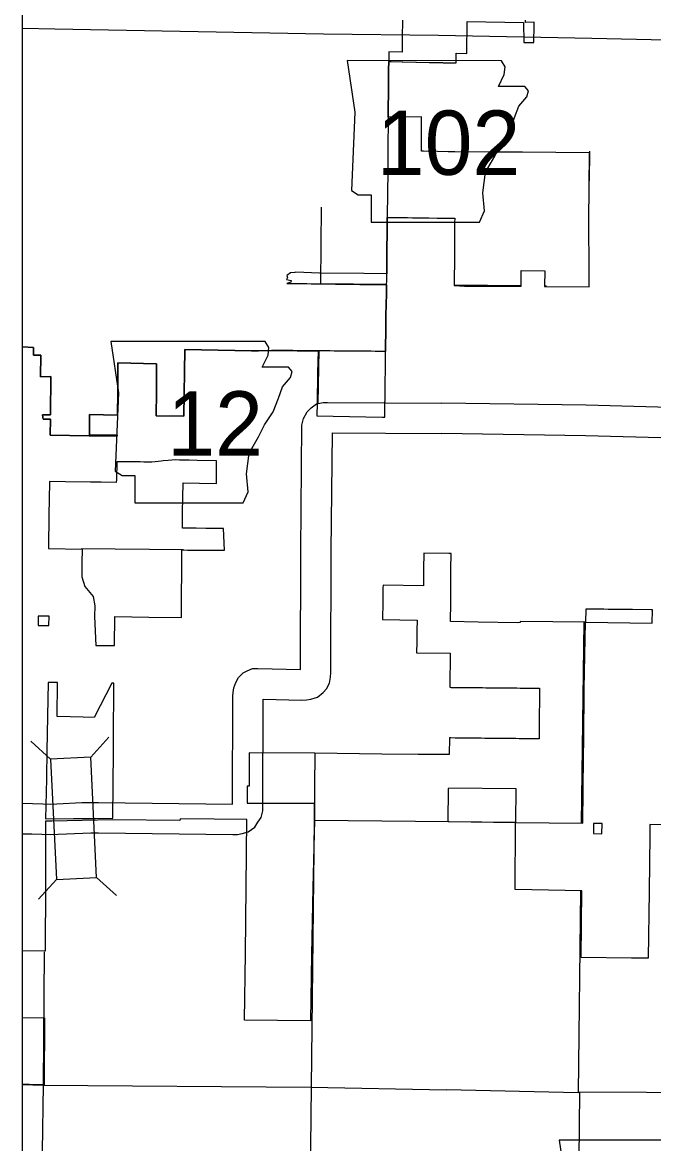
# Model space of a CAD drawing. Extents: x 309389.3 to 309420.2, y 336441.4 to 336461.2.
# Drawn here: x 309389.335 to 309390.277, y 336456.181 to 336457.854 of the extents above; entities that cross this region are included whole.
import ezdxf

# ---------------------------------------------------------------- set-up
doc = ezdxf.new("R2010")
doc.units = 0
for name, color, linetype in [('Level 24', 7, 'Continuous'), ('Level 37', 7, 'Continuous'), ('Level 4', 7, 'Continuous'), ('Level 62', 7, 'Continuous'), ('R_Contours', 7, 'Continuous'), ('R_MOT', 7, 'Continuous')]:
    doc.layers.add(name, color=color, linetype=linetype)

msp = doc.modelspace()

# ---------------------------------------------------------------- linework, layer by layer
at = {"layer": 'Level 24'}
for points in [[(309389.9561, 336457.8344), (309389.7843, 336457.8364), (309389.3834, 336457.8438), (309389.3351, 336457.8447)], [(309390.7673, 336457.8202), (309390.584, 336457.821), (309390.1849, 336457.8299), (309389.956, 336457.8344)], [(309389.3351, 336456.6888), (309389.3501, 336456.6885), (309389.3657, 336456.6881), (309389.3767, 336456.6876), (309389.3865, 336456.6879), (309389.424, 336456.6897), (309389.4366, 336456.6899), (309389.4487, 336456.6899), (309389.6486, 336456.6876), (309389.6492, 336456.8486), (309389.6496, 336456.8538), (309389.6506, 336456.8612), (309389.6535, 336456.8688), (309389.6575, 336456.8766), (309389.6648, 336456.8834), (309389.6706, 336456.8866), (309389.6784, 336456.8898), (309389.6867, 336456.8899), (309389.7499, 336456.8884), (309389.7506, 336457.0651), (309389.7523, 336457.253), (309389.7548, 336457.263), (309389.7599, 336457.273), (309389.7661, 336457.2789), (309389.7742, 336457.2848), (309389.7842, 336457.2867), (309389.7905, 336457.2869), (309389.8775, 336457.2863)], [(309389.8775, 336457.2863), (309389.9611, 336457.2858)], [(309390.8213, 336457.2733), (309390.5801, 336457.2731), (309390.5679, 336457.2721), (309390.1765, 336457.2827), (309389.9613, 336457.2858)], [(309389.3351, 336456.6433), (309389.3491, 336456.643), (309389.364, 336456.6427), (309389.3763, 336456.6421), (309389.3883, 336456.6424), (309389.4255, 336456.6442), (309389.437, 336456.6444), (309389.4485, 336456.6445), (309389.6493, 336456.6421), (309389.656, 336456.6423), (309389.6633, 336456.6434), (309389.6722, 336456.6463), (309389.6821, 336456.6532), (309389.6867, 336456.6604), (309389.6912, 336456.6673), (309389.6937, 336456.6775), (309389.6941, 336456.6851), (309389.6946, 336456.8442), (309389.752, 336456.8428), (309389.7589, 336456.8433), (309389.7657, 336456.8443), (309389.7757, 336456.8473), (309389.7838, 336456.854), (309389.789, 336456.8596), (309389.7934, 336456.8681), (309389.7951, 336456.877), (309389.7953, 336456.8841), (309389.7961, 336457.0648), (309389.7977, 336457.2414), (309389.8772, 336457.2409)], [(309389.8772, 336457.2409), (309389.9608, 336457.2403)], [(309390.8895, 336457.228), (309390.8636, 336457.2278), (309390.8461, 336457.2279), (309390.5819, 336457.2276), (309390.569, 336457.2266), (309390.1755, 336457.2373), (309389.9606, 336457.2403)]]:
    msp.add_lwpolyline(points, dxfattribs=at)
at = {"layer": 'Level 37'}
for p, q in [((309389.3772, 336456.7548), (309389.3476, 336456.7816)), ((309389.4371, 336456.7577), (309389.464, 336456.7873)), ((309389.386, 336456.575), (309389.3591, 336456.5454)), ((309389.4459, 336456.5779), (309389.4755, 336456.551))]:
    msp.add_line(p, q, dxfattribs=at)
msp.add_lwpolyline([(309389.3772, 336456.7548), (309389.386, 336456.575), (309389.4459, 336456.5779), (309389.4371, 336456.7577)], close=True, dxfattribs=at)
at = {"layer": 'Level 4'}
for points in [[(309390.1813, 336457.662), (309390.1807, 336457.6178)], [(309389.7809, 336457.5784), (309389.7799, 336457.4651)], [(309389.7799, 336457.4645), (309389.8787, 336457.4632)], [(309390.0793, 336457.4608), (309389.9796, 336457.4619)], [(309390.1175, 336457.4603), (309390.1144, 336457.4604)], [(309389.7777, 336457.3651), (309389.776, 336457.2857)], [(309389.5756, 336457.0667), (309389.4228, 336457.0682)], [(309390.1729, 336456.9592), (309390.1691, 336456.6591)], [(309389.7714, 336456.7636), (309389.7706, 336456.6632), (309389.766, 336456.2656), (309389.7616, 336455.8654), (309389.7546, 336455.4639)], [(309389.9722, 336456.661), (309389.7709, 336456.6629)], [(309390.0712, 336456.6598), (309389.9722, 336456.661)], [(309390.2001, 336456.6583), (309390.1875, 336456.6584)], [(309390.1679, 336456.5581), (309390.1643, 336456.2566)], [(309389.3572, 336455.4699), (309389.3608, 336455.8707), (309389.3666, 336456.2688), (309389.3681, 336456.467)], [(309389.3351, 336456.2689), (309389.3663, 336456.2683), (309389.7656, 336456.2653), (309389.968, 336456.2612)], [(309390.1643, 336456.2566), (309389.968, 336456.2612)]]:
    msp.add_lwpolyline(points, dxfattribs=at)
at = {"layer": 'Level 62'}
for points in [[(309389.9022, 336457.8575), (309389.902, 336457.8314), (309389.902, 336457.8098), (309389.8819, 336457.8099), (309389.8818, 336457.7957), (309389.8817, 336457.7833), (309389.8816, 336457.7731), (309389.8815, 336457.763), (309389.8811, 336457.7127), (309389.8807, 336457.6626), (309389.8803, 336457.6311), (309389.88, 336457.5997), (309389.8799, 336457.5968), (309389.8798, 336457.5851), (309389.8797, 336457.5776), (309389.8796, 336457.5643), (309389.8795, 336457.5631), (309389.8795, 336457.5543), (309389.8793, 336457.5323), (309389.8792, 336457.5229), (309389.8791, 336457.5131), (309389.8791, 336457.5074), (309389.879, 336457.4946), (309389.8789, 336457.4789), (309389.8445, 336457.4792), (309389.7786, 336457.48), (309389.743, 336457.4811), (309389.7417, 336457.4807), (309389.735, 336457.4804), (309389.7299, 336457.4761), (309389.7307, 336457.4732), (309389.7293, 336457.4701), (309389.7363, 336457.4687), (309389.7357, 336457.4662), (309389.7298, 336457.4646), (309389.7341, 336457.4645), (309389.7377, 336457.4646), (309389.7416, 336457.4644), (309389.7477, 336457.4644), (309389.7537, 336457.4643), (309389.7598, 336457.4642), (309389.7659, 336457.4641), (309389.7719, 336457.464), (309389.778, 336457.464), (309389.7789, 336457.4639), (309389.7841, 336457.4639), (309389.7901, 336457.4638), (309389.7961, 336457.4637), (309389.8022, 336457.4636), (309389.8082, 336457.4635), (309389.8143, 336457.4635), (309389.8203, 336457.4634), (309389.8263, 336457.4633), (309389.8324, 336457.4632), (309389.8385, 336457.4631), (309389.8446, 336457.4631), (309389.8506, 336457.463), (309389.8567, 336457.4629), (309389.8628, 336457.4628), (309389.8689, 336457.4627), (309389.8757, 336457.4627), (309389.8787, 336457.4625), (309389.8786, 336457.4538), (309389.8785, 336457.4533), (309389.8784, 336457.4463), (309389.8782, 336457.4356), (309389.8777, 336457.4145)], [(309389.8852, 336457.7956), (309389.9019, 336457.7953), (309389.9031, 336457.7953), (309389.9224, 336457.7948), (309389.9235, 336457.7948), (309389.9422, 336457.7944), (309389.9436, 336457.7944), (309389.9623, 336457.794), (309389.9633, 336457.7939), (309389.9825, 336457.7935), (309389.9826, 336457.8081), (309389.9986, 336457.8076), (309389.9987, 336457.8555), (309390.0831, 336457.8538), (309390.0834, 336457.8242), (309390.0985, 336457.8238), (309390.0989, 336457.8496), (309390.0989, 336457.8541), (309390.0858, 336457.8538), (309390.0858, 336457.8574)], [(309389.5348, 336457.2669), (309389.5761, 336457.2663), (309389.5774, 336457.3659), (309389.6772, 336457.3639), (309389.6873, 336457.3638), (309389.7068, 336457.3644), (309389.7183, 336457.3643), (309389.7197, 336457.3643), (309389.7259, 336457.3643), (309389.7323, 336457.3642), (309389.7387, 336457.3642), (309389.7451, 336457.3641), (309389.7472, 336457.3641), (309389.7519, 336457.364), (309389.758, 336457.364), (309389.7641, 336457.3639), (309389.7702, 336457.3639), (309389.7757, 336457.3638), (309389.7763, 336457.3638), (309389.7757, 336457.3309), (309389.7757, 336457.3303), (309389.775, 336457.2861), (309389.7747, 336457.2667), (309389.8721, 336457.2648), (309389.8761, 336457.2647), (309389.8766, 336457.3122), (309389.8769, 336457.3411), (309389.8771, 336457.363), (309389.8772, 336457.3677), (309389.8775, 336457.3951), (309389.8777, 336457.4145), (309389.8782, 336457.4356), (309389.8784, 336457.4463), (309389.8785, 336457.4533), (309389.8786, 336457.4538), (309389.8787, 336457.4625), (309389.8787, 336457.4629), (309389.8788, 336457.468), (309389.8789, 336457.4789), (309389.879, 336457.4946), (309389.8791, 336457.5091), (309389.8791, 336457.5131), (309389.8792, 336457.5229), (309389.8793, 336457.5323), (309389.8795, 336457.5543), (309389.8795, 336457.5631), (309389.8834, 336457.5631), (309389.8915, 336457.5629), (309389.9095, 336457.5627), (309389.9099, 336457.5627), (309389.9171, 336457.5626), (309389.9241, 336457.5625), (309389.9325, 336457.5624), (309389.9416, 336457.5623), (309389.9539, 336457.5621), (309389.9543, 336457.5621), (309389.9662, 336457.562), (309389.9699, 336457.5619), (309389.9803, 336457.5618), (309389.9802, 336457.5548), (309389.9802, 336457.5475), (309389.9801, 336457.5408), (309389.9801, 336457.5332), (309389.98, 336457.5297), (309389.98, 336457.5222), (309389.9799, 336457.5153), (309389.9799, 336457.5083), (309389.9799, 336457.5015), (309389.9798, 336457.4947), (309389.9798, 336457.4879), (309389.9797, 336457.4811), (309389.9797, 336457.4752), (309389.9796, 336457.4694), (309389.9796, 336457.4616), (309389.9796, 336457.4614), (309389.9951, 336457.4602), (309390.0793, 336457.4605), (309390.0795, 336457.4836), (309390.1146, 336457.4834), (309390.1147, 336457.4832), (309390.1144, 336457.4601), (309390.1808, 336457.4592), (309390.1809, 336457.4828), (309390.1803, 336457.5574), (309390.1814, 336457.6594), (309390.1313, 336457.6598), (309390.0815, 336457.6604), (309390.045, 336457.6606), (309389.9803, 336457.6609), (309389.9703, 336457.661), (309389.9546, 336457.6614), (309389.9337, 336457.6617), (309389.9305, 336457.6617), (309389.9305, 336457.7129), (309389.8811, 336457.7127), (309389.8815, 336457.763), (309389.8816, 336457.7731), (309389.8817, 336457.7833), (309389.8818, 336457.7957), (309389.8852, 336457.7956)], [(309389.8777, 336457.4145), (309389.8775, 336457.3951), (309389.8772, 336457.3677), (309389.8771, 336457.363), (309389.8745, 336457.363), (309389.8677, 336457.363), (309389.8616, 336457.3631), (309389.8555, 336457.3632), (309389.8494, 336457.3632), (309389.8433, 336457.3633), (309389.8372, 336457.3633), (309389.8311, 336457.3634), (309389.825, 336457.3634), (309389.8189, 336457.3635), (309389.8128, 336457.3635), (309389.8067, 336457.3636), (309389.8006, 336457.3636), (309389.7945, 336457.3637), (309389.7885, 336457.3637), (309389.7824, 336457.3638), (309389.777, 336457.3638), (309389.7763, 336457.3638), (309389.7757, 336457.3638), (309389.7702, 336457.3639), (309389.7641, 336457.3639), (309389.758, 336457.364), (309389.7519, 336457.364), (309389.7472, 336457.3641), (309389.7451, 336457.3641), (309389.7387, 336457.3642), (309389.7323, 336457.3642), (309389.7259, 336457.3643), (309389.7197, 336457.3643), (309389.7183, 336457.3643), (309389.7068, 336457.3644), (309389.6873, 336457.3638), (309389.6772, 336457.3639), (309389.5774, 336457.3659), (309389.5761, 336457.2663), (309389.5348, 336457.2669), (309389.5348, 336457.2685), (309389.5351, 336457.3012), (309389.5353, 336457.3229), (309389.5354, 336457.3445), (309389.4776, 336457.3462), (309389.4775, 336457.3245), (309389.4773, 336457.3028), (309389.4771, 336457.2677), (309389.4351, 336457.2688), (309389.435, 336457.2386), (309389.4766, 336457.2378), (309389.4765, 336457.2364), (309389.4349, 336457.2373), (309389.3766, 336457.2379), (309389.3769, 336457.2619), (309389.3661, 336457.2617), (309389.3656, 336457.2651), (309389.365, 336457.2685), (309389.3708, 336457.2683), (309389.377, 336457.2682), (309389.377, 336457.2691), (309389.3775, 336457.3254), (309389.3621, 336457.3253), (309389.3625, 336457.3572), (309389.3518, 336457.3574), (309389.3519, 336457.3691), (309389.3351, 336457.3697)], [(309389.3351, 336457.3697), (309389.3519, 336457.3691), (309389.3518, 336457.3574), (309389.3625, 336457.3572), (309389.3621, 336457.3253), (309389.3775, 336457.3254), (309389.377, 336457.2691), (309389.377, 336457.2682), (309389.3708, 336457.2683), (309389.365, 336457.2685), (309389.3656, 336457.2651), (309389.3661, 336457.2617), (309389.3769, 336457.2619), (309389.3766, 336457.2379), (309389.4349, 336457.2373), (309389.4765, 336457.2364), (309389.4766, 336457.2378), (309389.435, 336457.2386), (309389.4351, 336457.2688), (309389.4771, 336457.2677), (309389.4773, 336457.3028), (309389.4775, 336457.3245), (309389.4776, 336457.3462), (309389.5354, 336457.3445), (309389.5353, 336457.3229), (309389.5351, 336457.3012), (309389.5348, 336457.2685), (309389.5348, 336457.2669)], [(309390.169, 336456.4586), (309390.1702, 336456.5581), (309390.0703, 336456.56), (309390.0712, 336456.6575), (309390.0712, 336456.6602), (309390.0712, 336456.6602), (309390.1715, 336456.659), (309390.172, 336456.7095), (309390.1726, 336456.7586), (309390.1729, 336456.7839), (309390.1737, 336456.8597), (309390.1756, 336456.9592), (309390.0781, 336456.9599), (309390.078, 336456.9583), (309390.0745, 336456.9582), (309390.0154, 336456.9591), (309389.9742, 336456.9598), (309389.9742, 336456.9613), (309389.9744, 336456.987), (309389.9745, 336457.0127), (309389.9747, 336457.0383), (309389.9748, 336457.0614), (309389.9716, 336457.0614), (309389.934, 336457.0619), (309389.9338, 336457.0386), (309389.9335, 336457.0133), (309389.8733, 336457.0141), (309389.8732, 336457.0102), (309389.8732, 336457.0034), (309389.873, 336456.9923), (309389.873, 336456.989), (309389.8725, 336456.9628), (309389.9242, 336456.962), (309389.924, 336456.9465), (309389.9237, 336456.9298), (309389.9235, 336456.913), (309389.9736, 336456.9125), (309389.9729, 336456.8618), (309389.9752, 336456.8617), (309389.9815, 336456.8617), (309389.9862, 336456.8616), (309389.991, 336456.8616), (309389.9958, 336456.8615), (309390.0015, 336456.8615), (309390.0072, 336456.8614), (309390.0121, 336456.8614), (309390.017, 336456.8613), (309390.022, 336456.8613), (309390.0269, 336456.8612), (309390.0319, 336456.8612), (309390.0376, 336456.8611), (309390.0414, 336456.8611), (309390.0473, 336456.861), (309390.0524, 336456.861), (309390.0576, 336456.8609), (309390.0628, 336456.8609), (309390.0679, 336456.8608), (309390.0731, 336456.8608), (309390.0782, 336456.8607), (309390.0833, 336456.8607), (309390.0885, 336456.8606), (309390.0944, 336456.8605), (309390.0981, 336456.8605), (309390.1068, 336456.8604), (309390.1067, 336456.8526), (309390.1067, 336456.8488), (309390.1066, 336456.843), (309390.1066, 336456.838), (309390.1066, 336456.8331), (309390.1065, 336456.8282), (309390.1065, 336456.8233), (309390.1065, 336456.8183), (309390.1064, 336456.8134), (309390.1064, 336456.8085), (309390.1064, 336456.8036), (309390.1063, 336456.7989), (309390.1063, 336456.7906), (309390.1062, 336456.7848), (309390.0998, 336456.7849), (309390.0914, 336456.785), (309390.0865, 336456.785), (309390.0815, 336456.7851), (309390.0766, 336456.7851), (309390.0717, 336456.7852), (309390.0668, 336456.7852), (309390.0618, 336456.7853), (309390.0569, 336456.7853), (309390.052, 336456.7854), (309390.047, 336456.7854), (309390.0406, 336456.7855), (309390.0368, 336456.7855), (309390.0304, 336456.7856), (309390.0251, 336456.7856), (309390.0198, 336456.7857), (309390.0145, 336456.7858), (309390.0092, 336456.7858), (309390.0039, 336456.7859), (309389.9986, 336456.7859), (309389.9932, 336456.786), (309389.9871, 336456.786)], [(309389.9871, 336456.786), (309389.9811, 336456.7861), (309389.9746, 336456.7862), (309389.9723, 336456.7862), (309389.9718, 336456.7613), (309389.9255, 336456.7617), (309389.8716, 336456.7622), (309389.7715, 336456.7637), (309389.6737, 336456.7641), (309389.6734, 336456.7144), (309389.6706, 336456.7143), (309389.6703, 336456.6891), (309389.7711, 336456.6888), (309389.7711, 336456.687), (309389.771, 336456.6635), (309389.7687, 336456.5627), (309389.7677, 336456.5127), (309389.7668, 336456.4633), (309389.7653, 336456.3641), (309389.6667, 336456.3652), (309389.6679, 336456.4645), (309389.6689, 336456.5638), (309389.67, 336456.6646), (309389.6211, 336456.665), (309389.5704, 336456.6656), (309389.5703, 336456.6632), (309389.4701, 336456.664), (309389.379, 336456.6622), (309389.3698, 336456.662), (309389.3696, 336456.5682), (309389.3691, 336456.4679), (309389.3351, 336456.4683)], [(309390.4672, 336456.6764), (309390.4198, 336456.6769), (309390.419, 336456.6571), (309390.419, 336456.6554), (309390.3703, 336456.6563), (309390.3455, 336456.6565), (309390.2715, 336456.657), (309390.2715, 336456.6536), (309390.2713, 336456.6413), (309390.2703, 336456.5572), (309390.269, 336456.4574), (309390.2439, 336456.4577), (309390.169, 336456.4586)], [(309390.3681, 336456.4556), (309390.3532, 336456.4559), (309390.2938, 336456.457), (309390.2933, 336456.4094), (309390.2926, 336456.3561), (309390.3666, 336456.3549), (309390.3656, 336456.2793), (309390.3653, 336456.2551), (309390.2663, 336456.2569), (309390.1664, 336456.2575), (309390.1654, 336456.1577), (309390.1645, 336456.1081), (309390.1637, 336456.0585), (309390.2387, 336456.0577), (309390.24, 336456.1563), (309390.2653, 336456.1558), (309390.2641, 336456.0881), (309390.3639, 336456.0872), (309390.3635, 336456.0559)], [(309389.3351, 336456.3692), (309389.3679, 336456.3685), (309389.3674, 336456.2687), (309389.345, 336456.269), (309389.3351, 336456.2691)]]:
    msp.add_lwpolyline(points, dxfattribs=at)
for points in [[(309389.4725, 336456.9242), (309389.4731, 336456.9673), (309389.5236, 336456.9666), (309389.5724, 336456.966), (309389.5731, 336457.0667), (309389.5813, 336457.0666), (309389.5942, 336457.0665), (309389.6096, 336457.0664), (309389.6104, 336457.0664), (309389.615, 336457.0664), (309389.6263, 336457.0663), (309389.6365, 336457.0662), (309389.6354, 336457.0988), (309389.6087, 336457.0989), (309389.5945, 336457.0992), (309389.5738, 336457.0993), (309389.5738, 336457.1033), (309389.5742, 336457.1226), (309389.575, 336457.1667), (309389.5994, 336457.1664), (309389.6246, 336457.166), (309389.6246, 336457.1716), (309389.6247, 336457.1823), (309389.6247, 336457.1879), (309389.6248, 336457.1928), (309389.6248, 336457.1999), (309389.5957, 336457.2004), (309389.5839, 336457.2005), (309389.5809, 336457.2006), (309389.5751, 336457.2007), (309389.5695, 336457.2008), (309389.5638, 336457.201), (309389.5582, 336457.2006), (309389.5524, 336457.2001), (309389.5454, 336457.1996), (309389.5422, 336457.1993), (309389.533, 336457.1983), (309389.5285, 336457.1979), (309389.5246, 336457.198), (309389.5164, 336457.198), (309389.511, 336457.1981), (309389.5062, 336457.1981), (309389.5055, 336457.1981), (309389.4994, 336457.1982), (309389.4956, 336457.1982), (309389.4876, 336457.1983), (309389.4783, 336457.1984), (309389.4758, 336457.1984), (309389.4753, 336457.1717), (309389.4752, 336457.1673), (309389.4526, 336457.1677), (309389.4367, 336457.168), (309389.3995, 336457.1686), (309389.3755, 336457.169), (309389.3755, 336457.1675), (309389.3748, 336457.1187), (309389.3748, 336457.1171), (309389.3741, 336457.0719), (309389.374, 336457.0687), (309389.4241, 336457.068), (309389.4239, 336457.0473), (309389.4238, 336457.0316), (309389.4238, 336457.0267), (309389.4283, 336457.012), (309389.4406, 336456.9971), (309389.4434, 336456.9832), (309389.4429, 336456.9675), (309389.4449, 336456.9244)], [(309389.3748, 336456.9539), (309389.3751, 336456.9679), (309389.3587, 336456.9681), (309389.3585, 336456.9541)], [(309390.1756, 336456.9592), (309390.2751, 336456.9575), (309390.2753, 336456.9773), (309390.2734, 336456.9774), (309390.2458, 336456.9777), (309390.2393, 336456.9778), (309390.2327, 336456.9778), (309390.2262, 336456.9779), (309390.2197, 336456.978), (309390.2132, 336456.9781), (309390.2094, 336456.9781), (309390.203, 336456.9782), (309390.1966, 336456.9783), (309390.1901, 336456.9784), (309390.176, 336456.9785)], [(309389.4701, 336456.6663), (309389.4709, 336456.7664), (309389.471, 336456.7822), (309389.4717, 336456.8678), (309389.4688, 336456.8678), (309389.442, 336456.8166), (309389.426, 336456.817), (309389.3871, 336456.8182), (309389.3876, 336456.8689), (309389.3734, 336456.8691), (309389.3726, 336456.8185), (309389.3718, 336456.7664), (309389.371, 336456.7275), (309389.371, 336456.7253), (309389.3698, 336456.6655), (309389.4114, 336456.6658), (309389.4338, 336456.666), (309389.444, 336456.6661)], [(309390.0712, 336456.6602), (309389.9707, 336456.661), (309389.9712, 336456.7104), (309389.9713, 336456.7116), (309390.0716, 336456.711)], [(309390.1998, 336456.6433), (309390.2001, 336456.6585), (309390.1875, 336456.6587), (309390.1872, 336456.6435)]]:
    msp.add_lwpolyline(points, close=True, dxfattribs=at)
at = {"layer": 'R_Contours'}
for points in [[(309389.8198, 336457.7969), (309389.8313, 336457.72), (309389.8262, 336457.6033), (309389.8364, 336457.5969), (309389.8557, 336457.5969), (309389.8557, 336457.5559), (309390.0172, 336457.5559), (309390.0249, 336457.5726), (309390.0223, 336457.5995), (309390.0261, 336457.6303), (309390.0402, 336457.6546), (309390.0492, 336457.6726), (309390.062, 336457.6918), (309390.0697, 336457.7123), (309390.0761, 336457.7289), (309390.0877, 336457.743), (309390.0902, 336457.752), (309390.0851, 336457.7584), (309390.0454, 336457.7584), (309390.0543, 336457.7764), (309390.0556, 336457.7879), (309390.0503, 336457.7968)], [(309389.4671, 336457.3779), (309389.4787, 336457.301), (309389.4735, 336457.1844), (309389.4838, 336457.178), (309389.503, 336457.178), (309389.503, 336457.137), (309389.6645, 336457.137), (309389.6722, 336457.1536), (309389.6696, 336457.1805), (309389.6735, 336457.2113), (309389.6876, 336457.2356), (309389.6965, 336457.2536), (309389.7094, 336457.2728), (309389.7171, 336457.2933), (309389.7235, 336457.31), (309389.735, 336457.3241), (309389.7376, 336457.333), (309389.7324, 336457.3395), (309389.6927, 336457.3395), (309389.7017, 336457.3574), (309389.703, 336457.3689), (309389.6976, 336457.3778)], [(309390.1363, 336456.186), (309390.1478, 336456.1091), (309390.1427, 336455.9925), (309390.1529, 336455.9861), (309390.1722, 336455.9861), (309390.1722, 336455.9451), (309390.3336, 336455.9451), (309390.3413, 336455.9617), (309390.3388, 336455.9887), (309390.3426, 336456.0194), (309390.3567, 336456.0438), (309390.3657, 336456.0617), (309390.3785, 336456.0809), (309390.3862, 336456.1014), (309390.3926, 336456.1181), (309390.4041, 336456.1322), (309390.4067, 336456.1412), (309390.4016, 336456.1476), (309390.3618, 336456.1476), (309390.3708, 336456.1655), (309390.3721, 336456.1771), (309390.3668, 336456.1859)]]:
    msp.add_lwpolyline(points, close=True, dxfattribs=at)
at = {"layer": 'R_MOT'}
msp.add_lwpolyline([(309389.3351, 336459.8498), (309394.8545, 336459.8498), (309394.8545, 336455.3696), (309389.3351, 336455.3696)], close=True, dxfattribs=at)

# ---------------------------------------------------------------- texts
at = {"layer": 'R_Contours'}
for s, p in [('102', (309389.864, 336457.6265)), ('12', (309389.5513, 336457.2075))]:
    msp.add_text(s, height=0.096, dxfattribs=at).set_placement(p)

doc.saveas('drawing.dxf')
